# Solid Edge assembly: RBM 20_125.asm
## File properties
Title: Zylinder
Author: ahadarics
Template: iso metric assembly.asm
Last saved by: ahadarics
Revision: 12
Application: Solid Edge
Username: ahadarics
Dokumentum tartalom típus: 1
Document Number: RBM 20/125
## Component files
Profilrohr.par
Kolbenstange.par
Kit.par
Mutter_1.par
Mutter_2.par
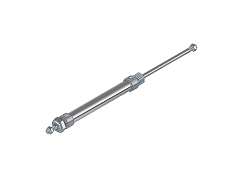
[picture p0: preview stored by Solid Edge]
